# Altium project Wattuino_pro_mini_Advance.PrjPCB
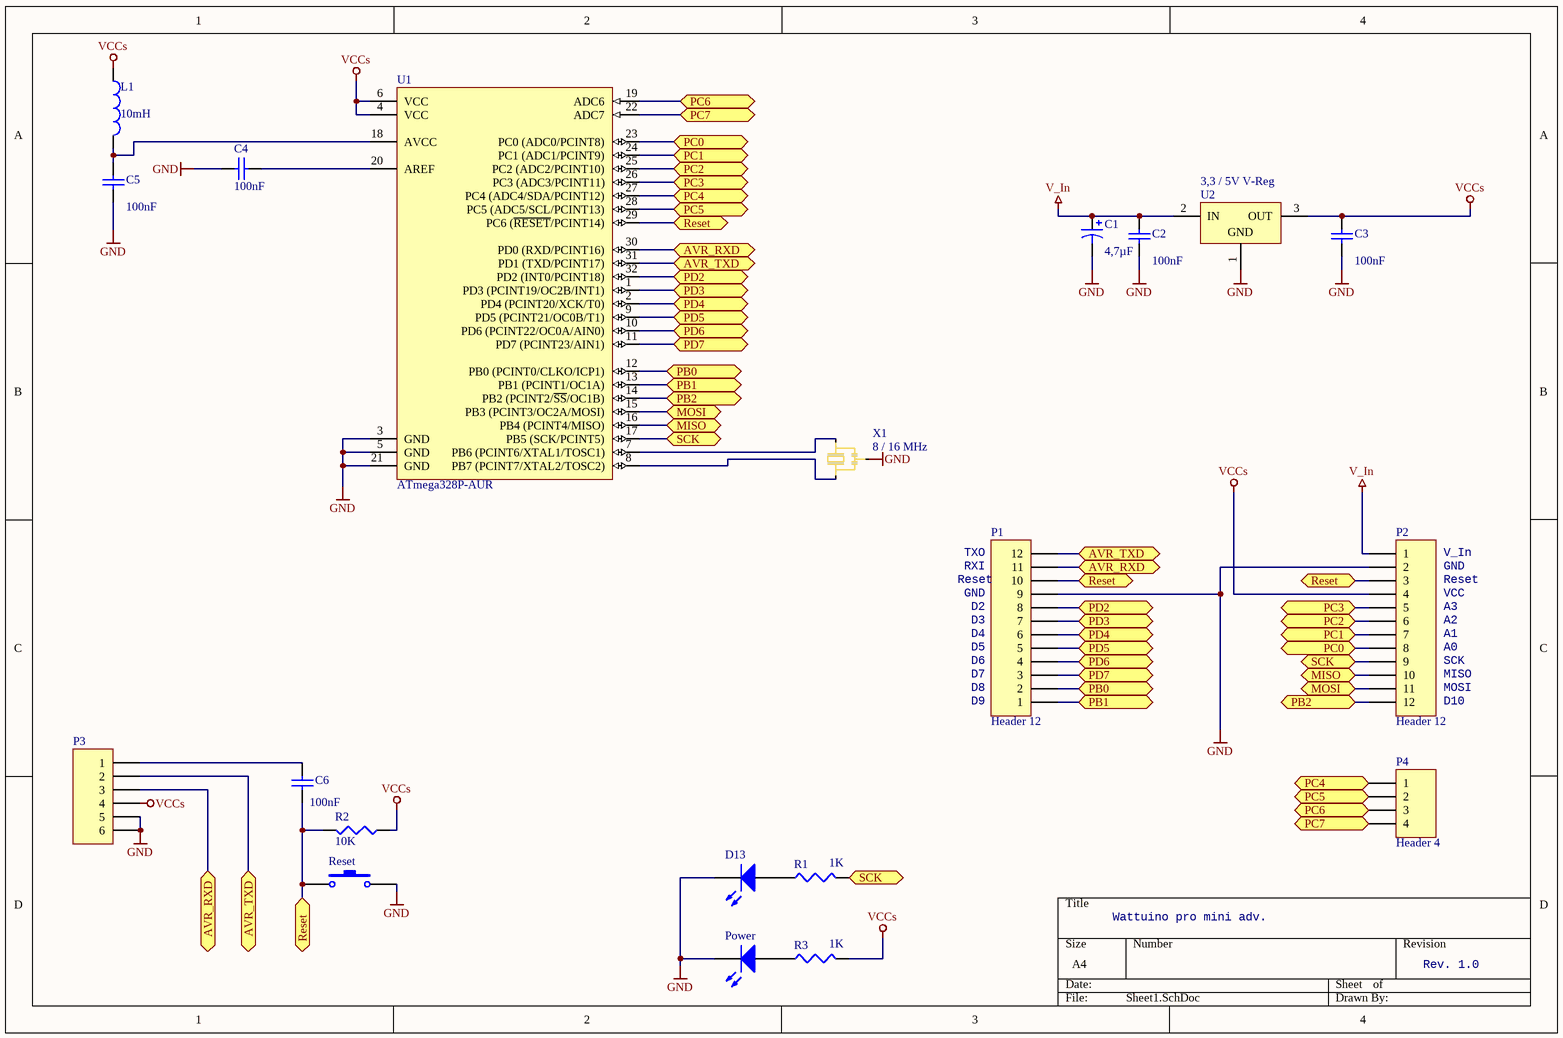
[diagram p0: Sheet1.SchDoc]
1 sheet, 20 parts. Net scope: flat (ports and power ports of the same name join across sheets).
Board file: PCB2.PcbDoc

## Sheet Sheet1.SchDoc
size A4

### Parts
C1  value 4,7µF  [C1206]  (hidden comment: Cap Pol1)
C2  value 100nF  [0603]  (hidden comment: C0603)
C3  value 100nF  [0603]  (hidden comment: C0603)
C4  value 100nF  [0603]  (hidden comment: C0603)
C5  value 100nF  [1608[0603]]  (hidden comment: C0603)
C6  value 100nF  [0603]  (hidden comment: C0603)
D13  LED2  [1608[0603]]  (value not drawn)
L1  value 10mH  [INDC1608L]  (hidden comment: Inductor)
P1  Header 12  [HDR1X12]
P2  Header 12  [HDR1X12]
P3  Header 6H  [HDR1X6]  (value not drawn)
P4  Header 4  [HDR1X4]
Power  LED2  [1608[0603]]  (value not drawn)
R1  value 1K  [1608[0603]]  (hidden comment: Res3)
R2  value 10K  [1608[0603]]  (hidden comment: Res3)
R3  value 1K  [1608[0603]]  (hidden comment: Res3)
Reset  SW-PB  [4u19182]  (value not drawn)
U1  ATmega328P-AUR  [32A_L]
U2  3,3 / 5V V-Reg  [SOT23_L]
X1  8 / 16 MHz  [CSTCE]

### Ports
AVR_RXD, AVR_TXD, MISO, MOSI, PB0, PB1, PB2, PC0, PC1, PC2, PC3, PC4, PC5, PC6, PC7, PD2, PD3, PD4, PD5, PD6, PD7, Reset, SCK

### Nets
GND: C1.2 C2.1 C3.1 C4.1 C5.1 D13.2(K) P1.9 P2.2 P3.5 P3.6 Power.2(K) Reset.3 U1.3(GND) U1.5(GND) U1.21(GND) U2.1(GND) X1.2
V_In: C1.1 C2.2 P2.1 U2.2(IN)
VCCs: C3.2 L1.1 P2.4 P3.4 R2.1 R3.2 U1.4(VCC) U1.6(VCC) U2.3(OUT)
NetC4_2: C4.2 U1.20(AREF)
NetC5_2: C5.2 L1.2 U1.18(AVCC)
NetC6_1: C6.1 P3.1
NetC6_2: C6.2 P1.10 P2.3 R2.2 Reset.1 U1.29(PC6_(~{RESET}/PCINT14)) ; port Reset
NetD13_1: D13.1(A) R1.1
NetP1_1: P1.1 U1.13(PB1_(PCINT1/OC1A)) ; port PB1
NetP1_2: P1.2 U1.12(PB0_(PCINT0/CLKO/ICP1)) ; port PB0
NetP1_3: P1.3 U1.11(PD7_(PCINT23/AIN1)) ; port PD7
NetP1_4: P1.4 U1.10(PD6_(PCINT22/OC0A/AIN0)) ; port PD6
NetP1_5: P1.5 U1.9(PD5_(PCINT21/OC0B/T1)) ; port PD5
NetP1_6: P1.6 U1.2(PD4_(PCINT20/XCK/T0)) ; port PD4
NetP1_7: P1.7 U1.1(PD3_(PCINT19/OC2B/INT1)) ; port PD3
NetP1_8: P1.8 U1.32(PD2_(INT0/PCINT18)) ; port PD2
NetP1_11: P1.11 P3.3 U1.30(PD0_(RXD/PCINT16)) ; port AVR_RXD
NetP1_12: P1.12 P3.2 U1.31(PD1_(TXD/PCINT17)) ; port AVR_TXD
NetP2_5: P2.5 U1.26(PC3_(ADC3/PCINT11)) ; port PC3
NetP2_6: P2.6 U1.25(PC2_(ADC2/PCINT10)) ; port PC2
NetP2_7: P2.7 U1.24(PC1_(ADC1/PCINT9)) ; port PC1
NetP2_8: P2.8 U1.23(PC0_(ADC0/PCINT8)) ; port PC0
NetP2_9: P2.9 R1.2 U1.17(PB5_(SCK/PCINT5)) ; port SCK
NetP2_10: P2.10 U1.16(PB4_(PCINT4/MISO)) ; port MISO
NetP2_11: P2.11 U1.15(PB3_(PCINT3/OC2A/MOSI)) ; port MOSI
NetP2_12: P2.12 U1.14(PB2_(PCINT2/~{SS}/OC1B)) ; port PB2
NetP4_1: P4.1 U1.27(PC4_(ADC4/SDA/PCINT12)) ; port PC4
NetP4_2: P4.2 U1.28(PC5_(ADC5/SCL/PCINT13)) ; port PC5
NetP4_3: P4.3 U1.19(ADC6) ; port PC6
NetP4_4: P4.4 U1.22(ADC7) ; port PC7
NetPower_1: Power.1(A) R3.1
NetU1_7: U1.7(PB6_(PCINT6/XTAL1/TOSC1)) X1.3
NetU1_8: U1.8(PB7_(PCINT7/XTAL2/TOSC2)) X1.1

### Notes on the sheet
- (near P1) Reset
- (near P1) TXO
- (near P1) RXI
- (near P2) Reset
- (near P2) GND
- (near P2) V_In
- (near P1) GND
- (near P1) D2
- (near P1) D3
- (near P1) D4
- (near P1) D5
- (near P2) A0
- (near P2) A1
- (near P2) A2
- (near P2) A3
- (near P2) VCC
- (near P1) D6
- (near P1) D7
- (near P1) D8
- (near P1) D9
- (near P2) D10
- (near P2) SCK
- (near P2) MISO
- (near P2) MOSI
- Wattuino pro mini adv.
- Rev. 1.0

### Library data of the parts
C1 = Cap Pol1: Polarized Capacitor (Radial)
C2-C6 = C0603: Ceramic Chip Capacitor - Standard; Note: Footprint corresponds to dimensions for bulk cassette packaging. This case size has tightened tolerances.
D13 Power = LED2: Typical RED, GREEN, YELLOW, AMBER GaAs LED
L1 = Inductor: Code_IEC: 1005
P1 P2 = Header 12: Header, 12-Pin
P3 = Header 6H: Header, 6-Pin, Right Angle
P4 = Header 4: Header, 4-Pin
R1-R3 = Res3: Resistor
Reset = SW-PB: Switch
U1 = ATmega328P-AUR: 8-bit AVR Microcontroller, 32KB Flash, 1KB EEPROM, 2KB SRAM, 32-pin TQFP, Industrial Grade (-40°C to 85°C)
U2 = µA78L05ACLP: Positive-Voltage Regulator
X1 = Resonator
